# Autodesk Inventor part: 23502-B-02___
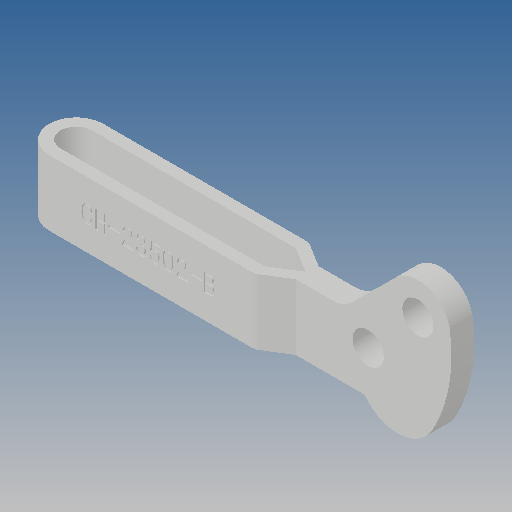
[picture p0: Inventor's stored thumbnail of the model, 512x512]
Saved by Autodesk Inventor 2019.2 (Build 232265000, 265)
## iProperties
Created: 2010-06
Part Number: 23502-B-02___
Material: Ogólny
Document SubType Name: Modeling
Designer: CADENGINEERING4
Density: 1 g/cm^3
Appearance: Domyślna
Author: CADENGINEERING4
Revision Number: ANY
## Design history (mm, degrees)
feature "NONE"
node "Bryła1"
